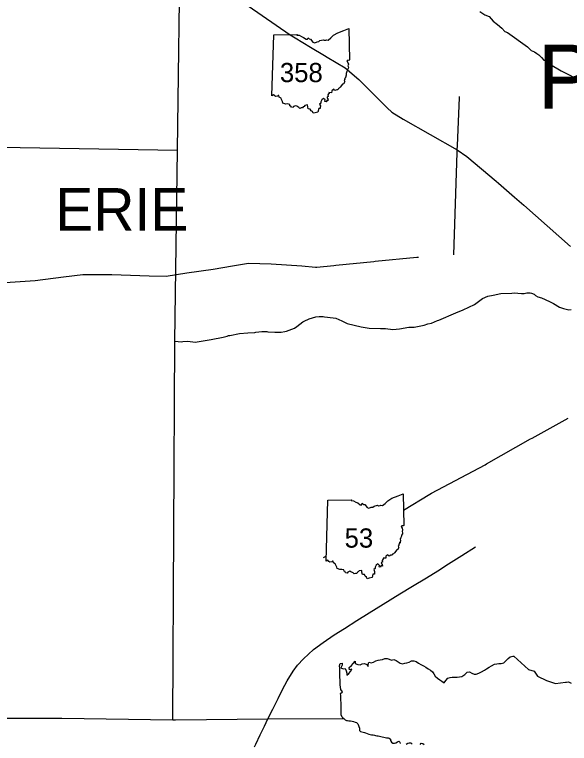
# Model space of a CAD drawing. Extents: x -232 to 448, y 619 to 1059.
# Drawn here: x 298.62 to 325.29, y 854.99 to 890 of the extents above; entities that cross this region are included whole.
import ezdxf

# ---------------------------------------------------------------- set-up
doc = ezdxf.new("R2010")
doc.units = 0
doc.layers.add('Default', color=7, linetype='Continuous')

msp = doc.modelspace()

# ---------------------------------------------------------------- linework, layer by layer
at = {"layer": 'Default'}
for p, q in [((310.988, 886.097), (311.07, 889.026)), ((310.988, 886.097), (311.07, 889.026)), ((313.594, 863.74), (313.676, 866.669)), ((313.594, 863.74), (313.676, 866.669))]:
    msp.add_line(p, q, dxfattribs=at)
for points in [[(306.452, 883.484), (306.59, 894.29), (311.799, 894.273), (311.845, 900.143)], [(305.944, 893.1), (306.564, 892.658), (307.395, 892.092), (309.168, 890.891), (311.867, 889.017), (312.099, 888.877), (312.84, 888.428), (313.511, 888.022)], [(320.986, 890.144), (321.215, 889.978), (321.42, 889.895), (321.617, 889.68), (321.826, 889.514), (322.035, 889.336), (322.184, 889.175), (322.303, 889.127), (323.265, 888.443), (323.451, 888.267), (323.605, 888.2), (323.712, 888.124), (323.81, 888.061), (323.939, 887.931), (324.06, 887.805), (324.22, 887.751), (324.394, 887.653), (324.382, 887.599), (324.884, 887.29), (325.274, 887.103), (325.52, 886.978)], [(311.07, 889.026), (312.207, 889.045), (312.189, 889.009), (312.296, 889.002), (312.41, 888.939), (312.506, 888.9), (312.624, 888.807), (312.695, 888.808), (312.724, 888.884), (312.778, 888.825), (312.843, 888.815), (312.953, 888.675), (313.045, 888.644), (313.154, 888.692), (313.236, 888.7), (313.296, 888.748), (313.452, 888.788), (313.495, 888.764), (313.578, 888.769), (313.62, 888.787), (313.692, 888.771), (313.818, 888.877), (313.949, 889.003), (314.149, 889.121), (314.449, 889.233), (314.686, 889.334), (314.721, 887.814)], [(311.07, 889.026), (312.207, 889.045), (312.189, 889.009), (312.296, 889.002), (312.41, 888.939), (312.506, 888.9), (312.624, 888.807), (312.695, 888.808), (312.724, 888.884), (312.778, 888.825), (312.843, 888.815), (312.953, 888.675), (313.045, 888.644), (313.154, 888.692), (313.236, 888.7), (313.296, 888.748), (313.452, 888.788), (313.495, 888.764), (313.578, 888.769), (313.62, 888.787), (313.692, 888.771), (313.818, 888.877), (313.949, 889.003), (314.149, 889.121), (314.449, 889.233), (314.686, 889.334), (314.721, 887.814)], [(314.721, 887.814), (314.686, 887.793), (314.631, 887.803), (314.594, 887.76), (314.64, 887.689), (314.661, 887.614), (314.642, 887.531), (314.661, 887.463), (314.648, 887.405), (314.614, 887.349), (314.602, 887.294), (314.573, 887.237), (314.576, 887.205), (314.548, 887.18), (314.553, 887.085), (314.539, 887.032), (314.544, 886.987), (314.499, 886.975), (314.509, 886.937), (314.48, 886.908), (314.486, 886.858), (314.454, 886.826), (314.485, 886.763), (314.46, 886.742), (314.439, 886.665), (314.381, 886.649), (314.266, 886.507), (314.225, 886.454), (314.179, 886.44), (314.154, 886.385), (314.098, 886.385), (314.012, 886.347), (313.957, 886.413), (313.86, 886.334), (313.849, 886.242), (313.727, 886.245), (313.732, 886.199), (313.704, 886.185), (313.68, 886.139), (313.694, 886.057), (313.637, 886.036), (313.644, 885.988), (313.68, 885.959), (313.697, 885.868), (313.636, 885.886), (313.586, 885.81), (313.535, 885.828), (313.552, 885.893), (313.465, 885.971), (313.383, 885.908), (313.34, 885.808), (313.34, 885.741), (313.279, 885.7), (313.318, 885.605), (313.311, 885.539), (313.312, 885.477), (313.236, 885.479), (313.19, 885.311)], [(314.721, 887.814), (314.686, 887.793), (314.631, 887.803), (314.594, 887.76), (314.64, 887.689), (314.661, 887.614), (314.642, 887.531), (314.661, 887.463), (314.648, 887.405), (314.614, 887.349), (314.602, 887.294), (314.573, 887.237), (314.576, 887.205), (314.548, 887.18), (314.553, 887.085), (314.539, 887.032), (314.544, 886.987), (314.499, 886.975), (314.509, 886.937), (314.48, 886.908), (314.486, 886.858), (314.454, 886.826), (314.485, 886.763), (314.46, 886.742), (314.439, 886.665), (314.381, 886.649), (314.266, 886.507), (314.225, 886.454), (314.179, 886.44), (314.154, 886.385), (314.098, 886.385), (314.012, 886.347), (313.957, 886.413), (313.86, 886.334), (313.849, 886.242), (313.727, 886.245), (313.732, 886.199), (313.704, 886.185), (313.68, 886.139), (313.694, 886.057), (313.637, 886.036), (313.644, 885.988), (313.68, 885.959), (313.697, 885.868), (313.636, 885.886), (313.586, 885.81), (313.535, 885.828), (313.552, 885.893), (313.465, 885.971), (313.383, 885.908), (313.34, 885.808), (313.34, 885.741), (313.279, 885.7), (313.318, 885.605), (313.311, 885.539), (313.312, 885.477), (313.236, 885.479), (313.19, 885.311)], [(313.511, 888.022), (313.643, 887.942), (314.503, 887.438), (315.159, 886.884), (315.804, 886.241), (316.003, 886.044), (316.521, 885.518), (316.754, 885.304), (317.291, 884.969), (319.895, 883.5)], [(313.19, 885.311), (313.057, 885.279), (312.965, 885.259), (312.932, 885.336), (312.867, 885.376), (312.824, 885.453), (312.729, 885.463), (312.707, 885.569), (312.696, 885.655), (312.567, 885.634), (312.532, 885.581), (312.486, 885.567), (312.459, 885.514), (312.397, 885.51), (312.33, 885.485), (312.286, 885.537), (312.176, 885.589), (312.126, 885.616), (312.023, 885.574), (312.001, 885.525), (311.919, 885.546), (311.9, 885.601), (311.85, 885.618), (311.839, 885.676), (311.733, 885.707), (311.651, 885.695), (311.508, 885.742), (311.499, 885.819), (311.45, 885.912), (311.425, 885.977), (311.334, 886.027), (311.316, 886.104), (311.287, 886.102), (311.26, 886.07), (311.159, 886.056), (311.119, 886.087), (311.063, 886.141), (310.988, 886.097)], [(313.19, 885.311), (313.057, 885.279), (312.965, 885.259), (312.932, 885.336), (312.867, 885.376), (312.824, 885.453), (312.729, 885.463), (312.707, 885.569), (312.696, 885.655), (312.567, 885.634), (312.532, 885.581), (312.486, 885.567), (312.459, 885.514), (312.397, 885.51), (312.33, 885.485), (312.286, 885.537), (312.176, 885.589), (312.126, 885.616), (312.023, 885.574), (312.001, 885.525), (311.919, 885.546), (311.9, 885.601), (311.85, 885.618), (311.839, 885.676), (311.733, 885.707), (311.651, 885.695), (311.508, 885.742), (311.499, 885.819), (311.45, 885.912), (311.425, 885.977), (311.334, 886.027), (311.316, 886.104), (311.287, 886.102), (311.26, 886.07), (311.159, 886.056), (311.119, 886.087), (311.063, 886.141), (310.988, 886.097)], [(319.904, 883.71), (320, 885.99), (320, 885.99), (320.002, 886.064)], [(273.973, 884.01), (279.293, 883.973), (282.013, 883.967), (284.683, 883.859), (306.452, 883.484)], [(319.895, 883.5), (319.904, 883.71)], [(306.325, 874.312), (306.452, 883.484)], [(319.733, 878.451), (319.892, 883.379), (319.895, 883.5)], [(319.895, 883.5), (320.356, 883.183), (321.759, 881.991), (321.871, 881.894)], [(321.871, 881.894), (322.643, 881.223)], [(322.643, 881.223), (323.089, 880.836), (325.34, 878.863)], [(298.078, 877.118), (298.397, 877.137), (299.601, 877.224), (300.965, 877.397), (301.903, 877.516), (303.294, 877.506), (305.081, 877.449), (305.907, 877.436), (306.891, 877.597), (308.158, 877.77), (309.088, 877.934), (309.866, 878.062), (310.944, 878.031), (312.431, 877.934), (313.078, 877.869), (313.147, 877.862), (313.956, 877.943), (314.053, 877.953), (315.885, 878.144), (315.952, 878.15), (317.947, 878.338), (317.947, 878.338), (318.038, 878.346)], [(306.325, 874.312), (306.638, 874.284), (306.7, 874.3), (306.935, 874.308), (307.179, 874.279), (307.294, 874.267), (308.065, 874.386), (308.649, 874.507), (308.833, 874.555), (308.897, 874.585), (308.956, 874.587), (309.426, 874.678), (309.833, 874.709), (310.159, 874.727), (310.215, 874.748), (310.493, 874.78), (310.737, 874.77), (310.795, 874.766), (311.123, 874.737), (311.43, 874.745), (311.61, 874.78), (311.682, 874.793), (312.076, 874.94), (312.184, 875.008), (312.475, 875.239), (312.539, 875.265), (312.774, 875.385), (313.09, 875.477), (313.264, 875.502), (313.453, 875.489), (313.512, 875.485), (313.937, 875.438), (314.051, 875.407), (314.34, 875.281), (314.595, 875.166), (315.273, 874.993), (315.661, 874.936), (316.212, 874.925), (316.441, 874.925), (316.796, 874.878), (317.124, 874.909), (317.569, 874.987), (317.827, 874.987), (318.061, 875.032), (318.3, 875.077), (318.483, 875.145), (318.659, 875.18), (318.952, 875.297), (319.005, 875.321), (319.831, 875.677), (320.184, 875.811), (320.715, 876.074), (321.112, 876.364), (321.364, 876.464), (321.616, 876.518), (321.991, 876.592), (322.516, 876.616), (322.637, 876.624), (322.983, 876.598), (323.113, 876.606), (323.233, 876.635), (323.406, 876.628), (323.469, 876.616), (323.592, 876.565), (323.656, 876.507), (323.766, 876.445), (323.943, 876.394), (324.33, 876.219), (324.517, 876.126), (324.802, 875.947), (325.001, 875.873), (325.251, 875.818), (325.363, 875.832)], [(306.219, 856.122), (306.325, 874.312)], [(317.31, 866.186), (318.577, 866.965), (318.652, 867.011), (321.239, 868.378), (321.3, 868.411), (323.421, 869.614), (323.487, 869.652), (325.231, 870.608)], [(313.676, 866.669), (314.813, 866.688), (314.795, 866.653), (314.902, 866.646), (315.016, 866.583), (315.112, 866.544), (315.23, 866.45), (315.301, 866.451), (315.33, 866.528), (315.384, 866.469), (315.448, 866.458), (315.559, 866.318), (315.651, 866.288), (315.76, 866.336), (315.842, 866.344), (315.902, 866.391), (316.058, 866.432), (316.101, 866.407), (316.184, 866.412), (316.225, 866.43), (316.298, 866.414), (316.424, 866.521), (316.555, 866.646), (316.755, 866.765), (317.055, 866.877), (317.292, 866.978), (317.327, 865.458)], [(313.676, 866.669), (314.813, 866.688), (314.795, 866.653), (314.902, 866.646), (315.016, 866.583), (315.112, 866.544), (315.23, 866.45), (315.301, 866.451), (315.33, 866.528), (315.384, 866.469), (315.448, 866.458), (315.559, 866.318), (315.651, 866.288), (315.76, 866.336), (315.842, 866.344), (315.902, 866.391), (316.058, 866.432), (316.101, 866.407), (316.184, 866.412), (316.225, 866.43), (316.298, 866.414), (316.424, 866.521), (316.555, 866.646), (316.755, 866.765), (317.055, 866.877), (317.292, 866.978), (317.327, 865.458)], [(317.327, 865.458), (317.292, 865.436), (317.237, 865.446), (317.2, 865.404), (317.246, 865.333), (317.267, 865.257), (317.248, 865.175), (317.267, 865.106), (317.254, 865.049), (317.22, 864.992), (317.208, 864.938), (317.179, 864.881), (317.181, 864.849), (317.154, 864.823), (317.159, 864.728), (317.145, 864.676), (317.15, 864.63), (317.105, 864.618), (317.115, 864.581), (317.086, 864.552), (317.092, 864.502), (317.06, 864.47), (317.091, 864.406), (317.066, 864.386), (317.045, 864.309), (316.987, 864.293), (316.872, 864.151), (316.831, 864.097), (316.785, 864.084), (316.76, 864.029), (316.704, 864.029), (316.618, 863.991), (316.563, 864.056), (316.466, 863.977), (316.455, 863.886), (316.333, 863.889), (316.338, 863.843), (316.31, 863.829), (316.286, 863.783), (316.3, 863.701), (316.243, 863.68), (316.25, 863.632), (316.286, 863.603), (316.303, 863.512), (316.242, 863.53), (316.192, 863.453), (316.141, 863.471), (316.158, 863.536), (316.071, 863.615), (315.989, 863.552), (315.946, 863.452), (315.946, 863.384), (315.885, 863.344), (315.924, 863.248), (315.917, 863.183), (315.918, 863.12), (315.842, 863.123), (315.796, 862.954)], [(317.327, 865.458), (317.292, 865.436), (317.237, 865.446), (317.2, 865.404), (317.246, 865.333), (317.267, 865.257), (317.248, 865.175), (317.267, 865.106), (317.254, 865.049), (317.22, 864.992), (317.208, 864.938), (317.179, 864.881), (317.181, 864.849), (317.154, 864.823), (317.159, 864.728), (317.145, 864.676), (317.15, 864.63), (317.105, 864.618), (317.115, 864.581), (317.086, 864.552), (317.092, 864.502), (317.06, 864.47), (317.091, 864.406), (317.066, 864.386), (317.045, 864.309), (316.987, 864.293), (316.872, 864.151), (316.831, 864.097), (316.785, 864.084), (316.76, 864.029), (316.704, 864.029), (316.618, 863.991), (316.563, 864.056), (316.466, 863.977), (316.455, 863.886), (316.333, 863.889), (316.338, 863.843), (316.31, 863.829), (316.286, 863.783), (316.3, 863.701), (316.243, 863.68), (316.25, 863.632), (316.286, 863.603), (316.303, 863.512), (316.242, 863.53), (316.192, 863.453), (316.141, 863.471), (316.158, 863.536), (316.071, 863.615), (315.989, 863.552), (315.946, 863.452), (315.946, 863.384), (315.885, 863.344), (315.924, 863.248), (315.917, 863.183), (315.918, 863.12), (315.842, 863.123), (315.796, 862.954)], [(310.793, 856.176), (311.031, 856.634), (311.284, 857.153), (311.494, 857.576), (311.724, 857.993), (311.999, 858.469), (312.219, 858.753), (312.507, 859.046), (312.991, 859.506), (313.448, 859.832), (313.985, 860.212), (314.475, 860.515), (315.063, 860.895), (315.66, 861.266), (316.339, 861.683), (317.134, 862.17), (317.741, 862.543), (318.41, 862.939), (318.961, 863.278), (319.476, 863.61), (320.114, 864.016), (320.77, 864.431)], [(313.469, 863.914), (313.601, 863.997)], [(315.796, 862.954), (315.663, 862.922), (315.571, 862.903), (315.538, 862.979), (315.473, 863.02), (315.43, 863.097), (315.335, 863.107), (315.313, 863.213), (315.302, 863.298), (315.173, 863.277), (315.137, 863.225), (315.092, 863.211), (315.065, 863.158), (315.003, 863.154), (314.936, 863.129), (314.892, 863.18), (314.782, 863.232), (314.732, 863.259), (314.629, 863.218), (314.607, 863.168), (314.525, 863.19), (314.506, 863.245), (314.456, 863.262), (314.445, 863.32), (314.339, 863.351), (314.257, 863.339), (314.114, 863.386), (314.105, 863.462), (314.056, 863.556), (314.031, 863.621), (313.94, 863.67), (313.922, 863.748), (313.893, 863.745), (313.866, 863.714), (313.765, 863.7), (313.725, 863.731), (313.669, 863.785), (313.594, 863.74)], [(315.796, 862.954), (315.663, 862.922), (315.571, 862.903), (315.538, 862.979), (315.473, 863.02), (315.43, 863.097), (315.335, 863.107), (315.313, 863.213), (315.302, 863.298), (315.173, 863.277), (315.137, 863.225), (315.092, 863.211), (315.065, 863.158), (315.003, 863.154), (314.936, 863.129), (314.892, 863.18), (314.782, 863.232), (314.732, 863.259), (314.629, 863.218), (314.607, 863.168), (314.525, 863.19), (314.506, 863.245), (314.456, 863.262), (314.445, 863.32), (314.339, 863.351), (314.257, 863.339), (314.114, 863.386), (314.105, 863.462), (314.056, 863.556), (314.031, 863.621), (313.94, 863.67), (313.922, 863.748), (313.893, 863.745), (313.866, 863.714), (313.765, 863.7), (313.725, 863.731), (313.669, 863.785), (313.594, 863.74)], [(314.364, 856.252), (314.316, 856.367), (314.31, 856.476), (314.316, 856.592), (314.318, 856.699), (314.318, 856.816), (314.312, 856.923), (314.304, 857.078), (314.298, 857.185), (314.294, 857.288), (314.281, 857.391), (314.386, 857.475), (314.292, 857.582), (314.279, 857.693), (314.267, 857.805), (314.265, 857.922), (314.259, 858.031), (314.248, 858.165), (314.244, 858.278), (314.255, 858.381), (314.248, 858.492), (314.242, 858.608), (314.24, 858.715), (314.259, 858.822), (314.366, 858.847), (314.36, 858.742), (314.304, 858.624), (314.407, 858.575), (314.51, 858.587), (314.555, 858.478), (314.592, 858.371), (314.582, 858.262), (314.687, 858.342), (314.769, 858.449), (314.822, 858.554), (314.718, 858.523), (314.703, 858.63), (314.812, 858.729), (314.888, 858.834), (314.981, 858.937), (314.991, 858.828), (315.117, 858.779), (315.222, 858.764), (315.326, 858.816), (315.435, 858.828), (315.542, 858.787), (315.606, 858.684), (315.617, 858.787), (315.651, 858.89), (315.756, 858.861), (315.87, 858.898), (315.979, 858.958), (316.088, 858.995), (316.195, 858.999), (316.299, 859.026), (316.406, 859.075), (316.518, 859.071), (316.627, 859.038), (316.734, 858.991), (316.841, 859.024), (316.95, 858.978), (317.052, 858.902), (317.157, 858.853), (317.26, 858.82), (317.375, 858.838), (317.478, 858.867), (317.583, 858.896), (317.694, 858.95), (317.809, 858.96), (317.921, 858.919), (318.028, 858.853), (318.143, 858.787), (318.268, 858.717), (318.377, 858.647), (318.497, 858.573), (318.604, 858.511), (318.711, 858.433), (318.766, 858.326), (318.832, 858.221), (318.945, 858.13), (319.052, 858.048), (319.155, 857.976), (319.262, 857.908), (319.352, 858.015), (319.443, 858.13), (319.546, 858.155), (319.655, 858.169), (319.78, 858.173), (319.891, 858.175), (320.007, 858.182), (320.116, 858.2), (320.255, 858.297), (320.369, 858.41), (320.476, 858.422), (320.589, 858.359), (320.7, 858.322), (320.805, 858.315), (320.936, 858.361), (321.064, 858.427), (321.196, 858.507)], [(321.196, 858.507), (321.305, 858.577), (321.43, 858.653), (321.533, 858.725), (321.691, 858.801), (321.794, 858.816), (321.897, 858.83), (322.008, 858.834), (322.125, 858.859), (322.228, 858.96), (322.335, 859.067), (322.442, 859.145), (322.572, 859.178), (322.612, 859.18)], [(322.612, 859.18), (323.325, 858.549), (323.597, 858.459), (323.746, 858.221), (324.176, 858.008), (324.621, 857.861), (325.099, 857.929)], [(325.099, 857.929), (325.137, 857.926), (325.24, 857.953), (325.361, 857.888)], [(273.981, 856.583), (290.19, 856.341), (295.448, 856.203), (300.895, 856.201), (306.219, 856.122)], [(314.364, 856.252), (314.438, 856.19)], [(306.219, 856.122), (306.354, 856.12), (310.812, 856.176), (314.438, 856.19)], [(310.153, 854.822), (310.209, 854.949), (310.427, 855.407), (310.633, 855.822), (310.793, 856.176)], [(314.438, 856.19), (314.444, 856.185), (314.448, 856.18), (314.503, 856.121), (314.571, 856.096), (314.626, 856.085), (314.69, 856.08), (314.764, 856.081), (314.838, 856.062), (314.91, 856.044), (314.984, 856.019), (315.049, 855.989), (315.11, 855.926), (315.155, 855.858), (315.171, 855.804), (315.188, 855.727), (315.194, 855.674), (315.197, 855.618), (315.236, 855.56), (315.306, 855.543), (315.371, 855.534), (315.435, 855.516), (315.49, 855.497), (315.568, 855.467), (315.638, 855.44), (315.702, 855.422), (315.776, 855.409), (315.845, 855.398), (315.911, 855.385), (315.971, 855.376), (316.024, 855.363), (316.088, 855.35), (316.158, 855.336), (316.227, 855.317), (316.287, 855.304), (316.357, 855.287), (316.427, 855.273), (316.497, 855.264), (316.566, 855.257), (316.628, 855.248), (316.681, 855.194), (316.693, 855.128), (316.729, 855.057), (316.8, 855.005), (316.872, 854.998), (316.942, 855.018), (317.017, 855.072), (317.085, 855.098), (317.128, 855.046), (317.148, 854.99)], [(317.442, 854.958), (317.511, 855.004), (317.581, 855.022), (317.655, 855.013), (317.722, 854.95)], [(318.109, 854.937), (318.165, 855.009), (318.233, 854.991), (318.298, 854.945)]]:
    msp.add_lwpolyline(points, dxfattribs=at)

# ---------------------------------------------------------------- texts
for s, height, p in [('PORT CLINTON', 3.07799, (323.758, 885.477)), ('358', 0.9234, (311.369, 886.75)), ('ERIE', 2.052, (300.568, 879.611)), ('53', 0.9234, (314.48, 864.394))]:
    msp.add_text(s, height=height, dxfattribs=at).set_placement(p)

doc.saveas('drawing.dxf')
